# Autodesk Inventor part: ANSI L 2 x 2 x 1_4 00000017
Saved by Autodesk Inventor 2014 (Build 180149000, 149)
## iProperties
_FrameMemberDoc: Frame Member File
_Version: 12.0.0
_CCFamilyMember: 11
_CCFamilyDisplayName: ANSI L (Equal angles) - Angle Steel
Created: 2007-02
Part Number: ANSI L 2 x 2 x 1_4 00000017
Material: Steel, Mild
Document SubType Name: Modeling
Standard: ANSI
Designer: hendert
Size Designation: L 2 x 2 x 1/4
Stock Number: L 2 x 2 x 1/4
Density: 1 g/cm^3
Appearance: Steel
G_L: 30.754 in
G_W: 2.000 in
G_H: 2.000 in
+093B49A2-D133-42F0-9844-518DC2C58F0E+CUTDETAIL1: Cut
+96888D84-C086-4B55-9F6F-F09268024C35+CUTDETAIL2: Cut
Author: hendert
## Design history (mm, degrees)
node "Start plane"
node "End plane"
sketch "Sketch"
  geometry: L1 (50.8, 0)-(0, 0); L2 (0, 0)-(0, 50.8); L3 (0, 50.8)-(3.302, 50.8); L4 (6.35, 47.752)-(6.35, 12.7); L5 (12.7, 6.35)-(47.752, 6.35); L6 (50.8, 3.302)-(50.8, 0); L7 (0, -11.041)-(0, 31.538); L8 (-11.041, 0)-(31.538, 0); L9 (0, 63.926)-(0, -23.536) reference; L10 (-23.536, 0)-(63.926, 0) reference; A1 r 6.35 centre (12.7, 12.7) between (6.35, 12.7) and (12.7, 6.35); A2 r 3.048 centre (3.302, 47.752) between (6.35, 47.752) and (3.302, 50.8); A3 r 3.048 centre (47.752, 3.302) between (50.8, 3.302) and (47.752, 6.35); 3 further points
  constraints: 16 end point, 6 point on circle, 6 point on line, 6 tangent, 4 parallel, 3 centre point, 2 collinear, 1 equal radius, 1 horizontal, 1 perpendicular
  dimensions: "d0" = 50.8 distance between parallel lines of L6 L2 (= G_H); "d1" = 50.8 distance between parallel lines of L3 L1 (= G_H); "d2" = 6.35 distance between parallel lines of L2 L4 (= G_T); "d3" = 6.35 distance between parallel lines of L1 L5 (= G_T); "d10" = 0 distance between parallel lines of L7 L2 (computed from ex); "d11" = 0 distance between parallel lines of L8 L1 (computed from d10); "d14" = 6.35 radius of A1 (= G_IR); "d15" = 3.048 radius of A2 (= G_ER)
extrude "Body" new body sketch "Sketch" stored distance "d4" = 781.15556 (= G_L); taper "d5" = 0 deg
workplane "Work Plane3"
split "Split1"
workplane "Work Plane4"
split "Split2"
body "Solid1"
other parameters: "G_H" = 50.8 [user parameter; used in 2 equation terms], "G_T" = 6.35 [user parameter; used in 2 equation terms], "G_ER" = 3.048 [user parameter; used in 1 equation term], "G_IR" = 6.35 [user parameter; used in 1 equation term], "G_L" = 781.15556 (= B_L + G_OFFSET_START + G_OFFSET_END) [user parameter; used in 1 equation term], "ex" = 0 [user parameter; used in 1 equation term], "G_OFFSET_START" = -14.68216 [user parameter; used in 2 equation terms], "G_OFFSET_END" = 5.47199 [user parameter; used in 2 equation terms], "d12" = 14.68216 (= -G_OFFSET_START), "d13" = 795.83771 (= G_OFFSET_END + B_L), "B_L" = 790.36573 [user parameter; used in 2 equation terms]
